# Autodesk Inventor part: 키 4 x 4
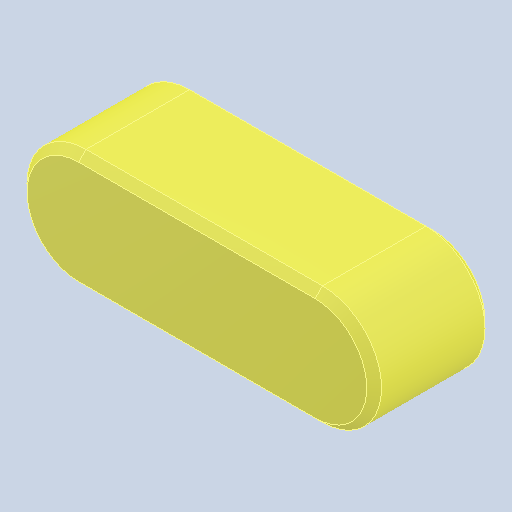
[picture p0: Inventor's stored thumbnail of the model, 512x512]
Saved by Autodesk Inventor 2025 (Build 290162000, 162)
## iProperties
Created: 2024-08
Part Number: 키 4 x 4
Material: 강철, 연강
Description: 키 및 해당 키홈
Document SubType Name: Modeling
Designer: hsj03
Density: 7.86 g/cm^3
Appearance: 기본값
Author: jhkim
Sending System: Autodesk Inventor 2025
Preprocessor: ST-DEVELOPER v20
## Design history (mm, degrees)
feature "Solid1"
node "솔리드1"
